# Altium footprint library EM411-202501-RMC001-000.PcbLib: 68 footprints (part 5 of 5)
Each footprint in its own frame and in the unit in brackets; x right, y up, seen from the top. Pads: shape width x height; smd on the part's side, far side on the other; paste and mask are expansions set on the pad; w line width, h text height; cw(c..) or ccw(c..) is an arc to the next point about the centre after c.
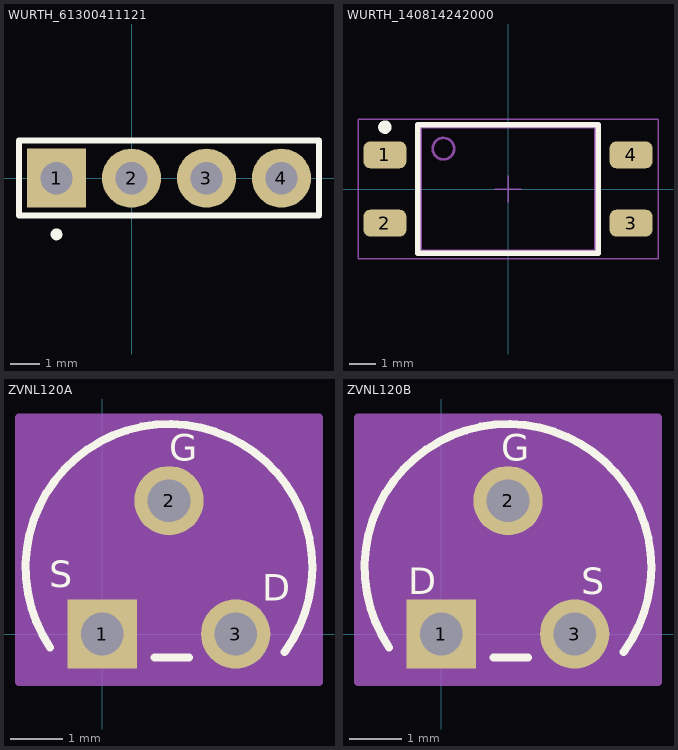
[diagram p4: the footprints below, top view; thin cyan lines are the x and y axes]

## WURTH_61300411121 [mm]
height 7.4
pads (4):
  rect 2x2 hole 1.1: 1(-2.54,0)
  round 2 hole 1.1: 2(0,0) 3(2.54,0) 4(5.08,0)
Top Overlay:
  circle w0.2: c-2.54,-1.905 r0.1
  lines w0.2: -3.81,-1.27 -3.81,1.27 6.35,1.27 6.35,-1.27 -3.81,-1.27
3D body "61300411121.stp": height 8.59, standoff -2.95, extent -3.81,-1.27 6.35,1.27

## WURTH_140814242000 [mm] "Optocoupler Phototransistor, body 6.5x4.58mm"
height 4.3
pads (4):
  rrect50% 1.6x1 smd: 1(-4.575,1.27) 2(-4.575,-1.27) 3(4.575,-1.27) 4(4.575,1.27)
Top Overlay:
  circle w0.25: c-4.575,2.3 r0.125
  lines w0.2: -3.35,-2.39 -3.35,2.39 3.35,2.39 3.35,-2.39 -3.35,-2.39
Top 3D Body:
  circle w0.1: c-2.4,1.5 r0.4
  lines w0.1: -3.25,-2.29 3.25,-2.29 3.25,2.29 -3.25,2.29 -3.25,-2.29
Top Courtyard:
  lines w0.05: -0.5,0 0.5,0 ; 0,-0.5 0,0.5 ; -5.575,-2.59 5.575,-2.59 5.575,2.59 -5.575,2.59 -5.575,-2.59
Top Component Outline:
  circle w0.1: c-2.4,1.5 r0.4
  lines w0.1: -3.25,-2.29 -3.25,2.29 3.25,2.29 3.25,-2.29 -3.25,-2.29
3D body "WL-OCTP_DIP4_816_S_rev1.stp": height 4.3, standoff -0.01, extent -5.075,-2.29 5.075,2.29

## ZVNL120A [mil]
pads (3):
  rect 52x52 hole 32 paste-99999 mask+0: 1(0,0)
  round 52 hole 32 paste-99999 mask+0: 2(50,100) 3(100,0)
Top Overlay:
  lines w6: -39.1,-10.15 cw(c50,50) 157.5,50 cw(c50,50) 136.65,-13.63 ; 39.1,-17.5 65.03,-17.5
  text "D" at 120,25 h20
  text "G" at 50,130 h20
  text "S" at -40,35 h20
Mechanical 13:
  circle w1: c-42.5,0 r5
  lines w1: -31.24,-12.5 cw(c50,50) 131.24,-12.5 -31.24,-12.5
  lines w6: -10,0 10,0 ; 0,-10 0,10
Mechanical 15:
  region: 162.5,-36 -62.5,-36 -62.5,162.5 162.5,162.5
  lines w6: -62.5,-36 162.5,-36 162.5,162.5 -62.5,162.5 -62.5,-36
3D body "TO-92_FAS.step": height 290, standoff -107.99, extent -52.39,-10.98 152.39,152.04

## ZVNL120B [mil]
pads (3):
  rect 52x52 hole 32 paste-99999 mask+0: 1(0,0)
  round 52 hole 32 paste-99999 mask+0: 2(50,100) 3(100,0)
Top Overlay:
  lines w6: -39.1,-10.15 cw(c50,50) 157.5,50 cw(c50,50) 136.65,-13.63 ; 39.1,-17.5 65.03,-17.5
  text "D" at -25,30 h20
  text "G" at 45,130 h20
  text "S" at 105,30 h20
Mechanical 13:
  circle w1: c-42.5,0 r5
  lines w1: -31.24,-12.5 cw(c50,50) 131.24,-12.5 -31.24,-12.5
  lines w6: -10,0 10,0 ; 0,-10 0,10
Mechanical 15:
  region: 162.5,-36 -62.5,-36 -62.5,162.5 162.5,162.5
  lines w6: -62.5,-36 162.5,-36 162.5,162.5 -62.5,162.5 -62.5,-36
3D body "TO-92_FAS.step": height 290, standoff -107.99, extent -52.39,-10.98 152.39,152.04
